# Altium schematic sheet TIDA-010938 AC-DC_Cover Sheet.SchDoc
size 431 x 279 mm; Date: Not shown in title block; ApprovedBy: Not shown in title block; CheckedBy: Not shown in title block; Author: Not shown in title block; CompanyName: Not shown in title block; Engineer: Not shown in title block; Organization: Not shown in title block; Address1: Not shown in title block; Address2: Not shown in title block; Address3: Not shown in title block; Address4: Not shown in title block; DocumentNumber: 8; Revision: Use project parameter SCH_Rev; SheetNumber: 2; SheetTotal: 11; PageSetup: Record=PageOptions¦CenterHorizontal=True¦CenterVertical=True¦PrintScale=1.00¦XCorrection=1.00¦YCorrection=1.00¦PrintKind=0¦BorderSize=5000000¦LeftOffset=0¦BottomOffset=0¦Orientation=2¦PaperLength=1000¦PaperWidth=1000¦Scale=100¦PaperSource=15¦PrintQuality=600¦MediaType=1¦DitherType=10¦PaperKind=Letter¦PrintScaleMode=1
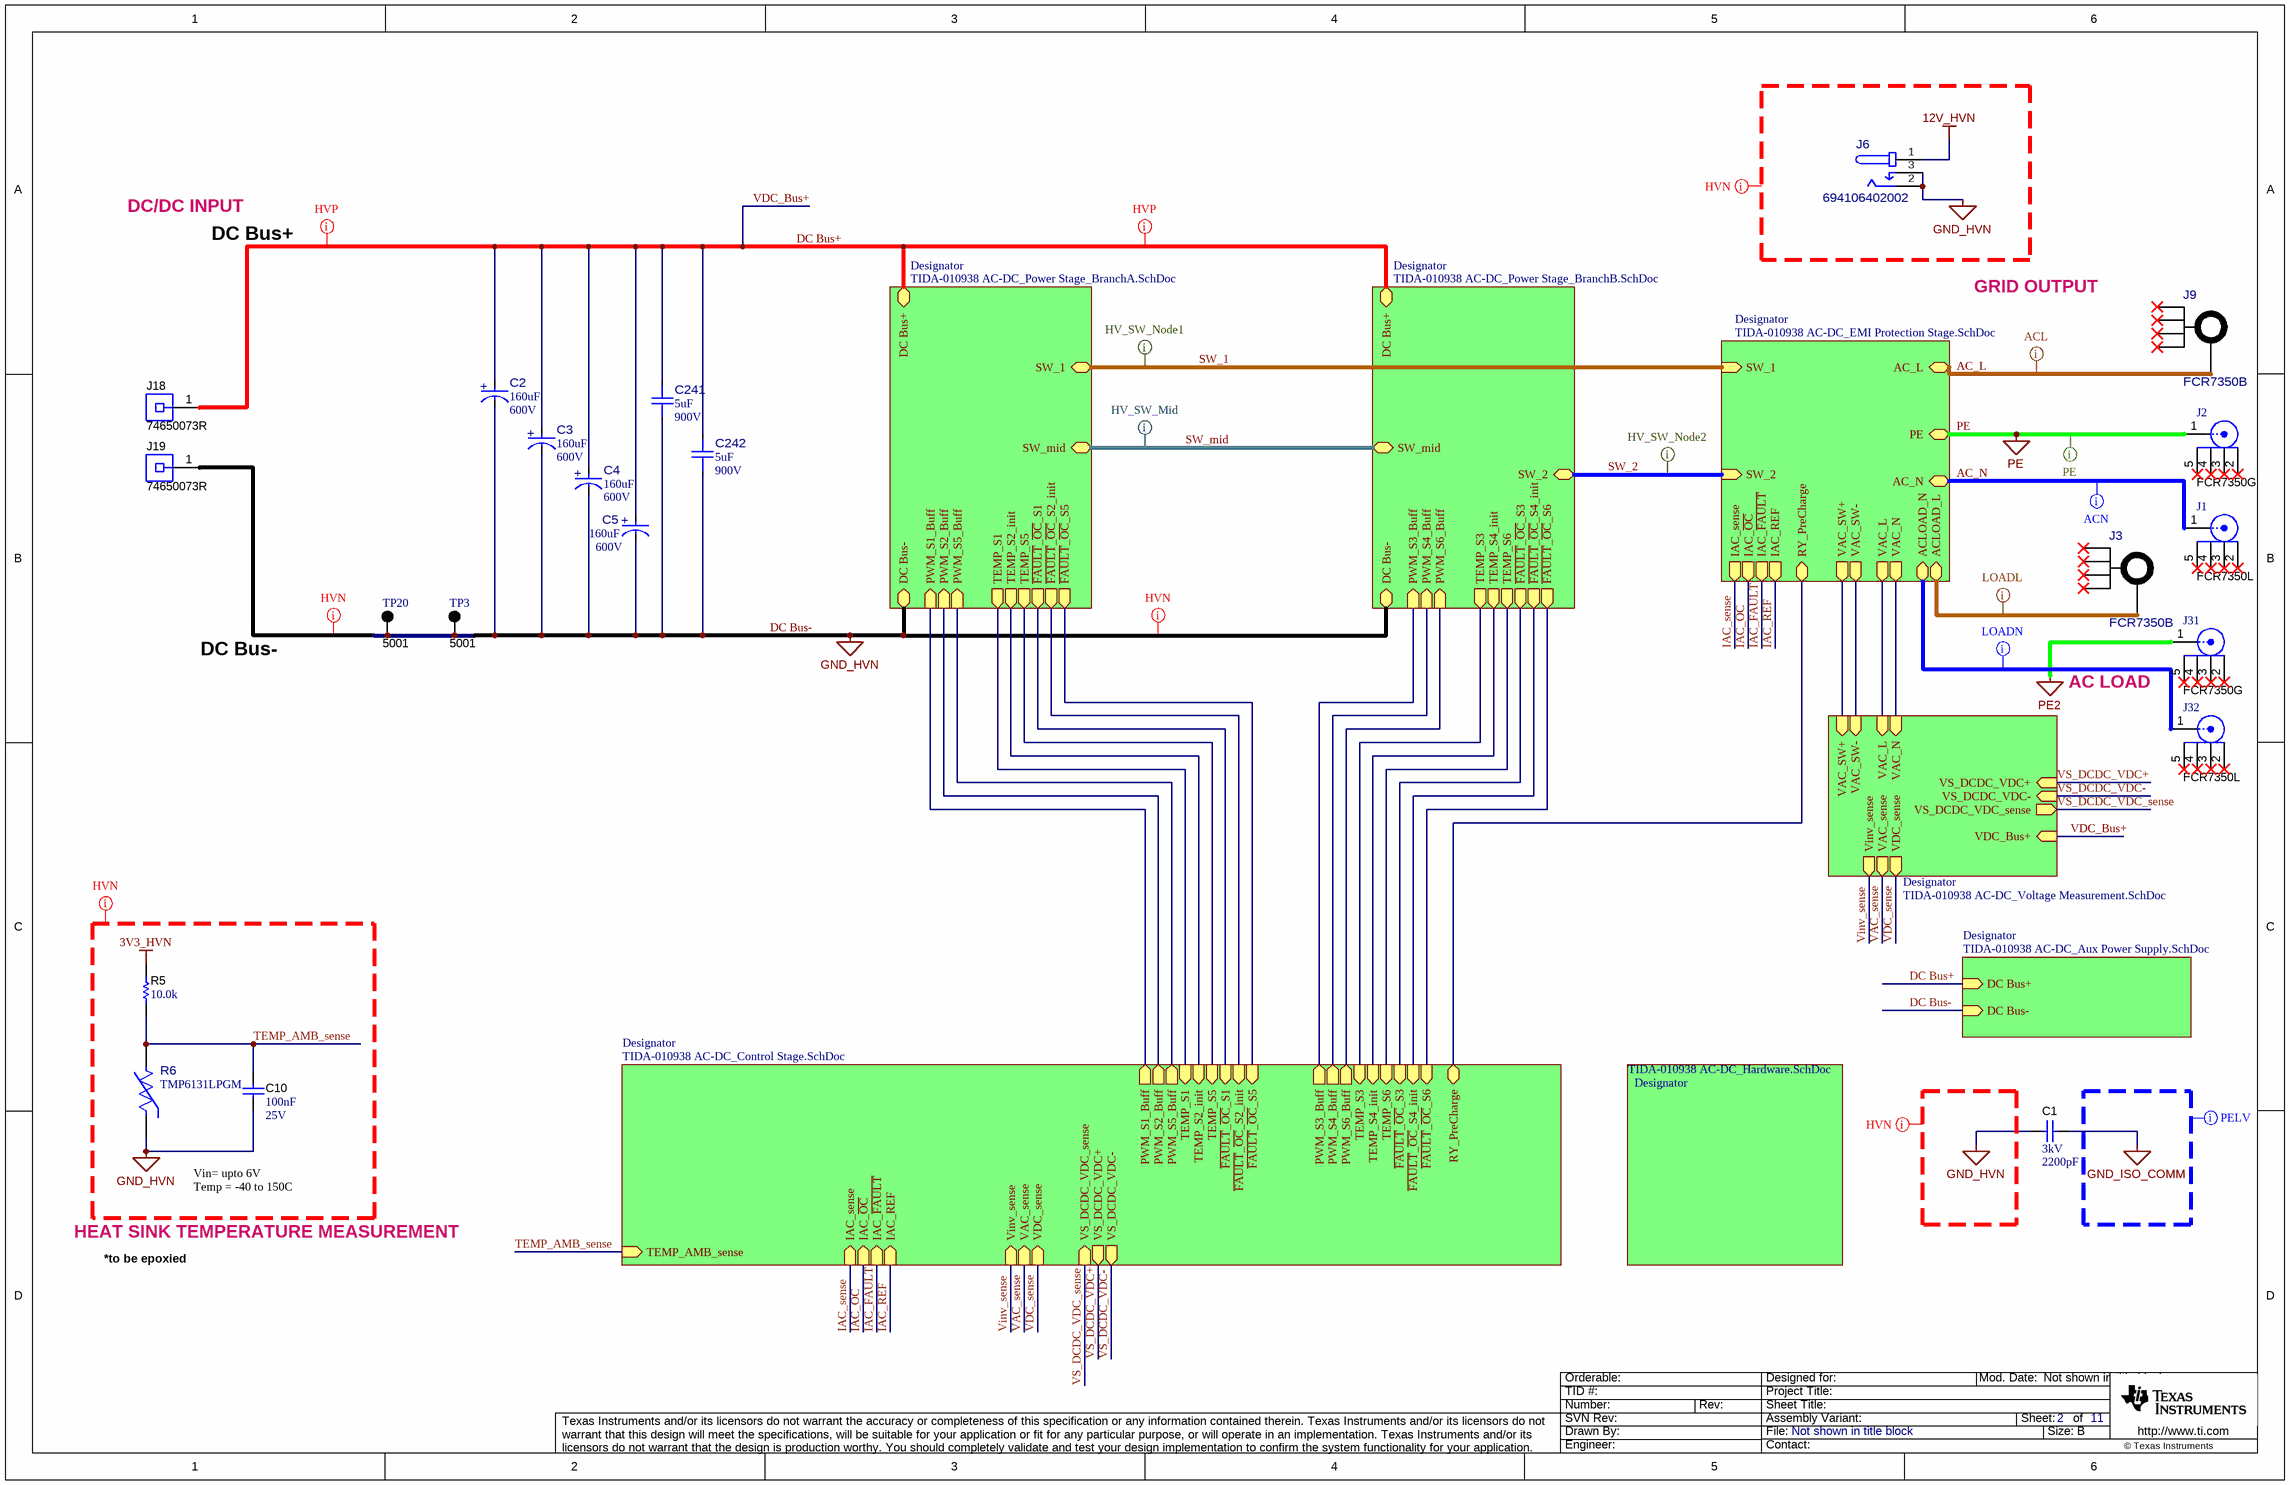
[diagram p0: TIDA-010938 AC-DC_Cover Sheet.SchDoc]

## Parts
C1  VDC_V: 3kV  ValueDisplayed: 2200pF  [CK45_1250x600x1650]  (hidden comment: CK45-B3FD222KYVNA)
C2  ValueDisplayed: 160uF  VDC_V: 600V  [FP-ALH82D161DD600_RADIAL-MFG]  (hidden comment: ALH82D161DD600)
C3  ValueDisplayed: 160uF  VDC_V: 600V  [FP-ALH82D161DD600_RADIAL-MFG]  (hidden comment: ALH82D161DD600)
C4  ValueDisplayed: 160uF  VDC_V: 600V  [FP-ALH82D161DD600_RADIAL-MFG]  (hidden comment: ALH82D161DD600)
C5  ValueDisplayed: 160uF  VDC_V: 600V  [FP-ALH82D161DD600_RADIAL-MFG]  (hidden comment: ALH82D161DD600)
C10  Cap_F: 100nF  VDC_V: 25V  [0603]  (hidden comment: 06033C104JAT2A)
C241  ValueDisplayed: 5uF  VDC_V: 900V  [FP-C4AKOBU4500A31J_RADIAL-MFG]  (hidden comment: C4AKOBU4500A31J)
C242  ValueDisplayed: 5uF  VDC_V: 900V  [FP-C4AKOBU4500A31J_RADIAL-MFG]  (hidden comment: C4AKOBU4500A31J)
J1  FCR7350L  [FP-FCR7350L_CONN_BANANA_JACK-MFG]
J2  FCR7350G  [FP-FCR7350G_CONN_BANANA_JACK-MFG]
J3  FCR7350B  [FP-FCR7350B_CONN_BANANA_JACK-MFG]
J6  694106402002  [FP-694106402002_CONN_PWR_10MM7_9MM0-MFG]
J9  FCR7350B  [FP-FCR7350B_CONN_BANANA_JACK-MFG]
J18  74650073R  [Wurth_WP-THRBU]
J19  74650073R  [Wurth_WP-THRBU]
J31  FCR7350G  [FP-FCR7350G_CONN_BANANA_JACK-MFG]
J32  FCR7350L  [FP-FCR7350L_CONN_BANANA_JACK-MFG]
R5  ValueDisplayed: 10.0k  [0603]  (hidden comment: RG1608P-103-B-T5)
R6  TMP6131LPGM  [LPG0002A-MFG]
TP3  5001  [Keystone5001]
TP20  5001  [Keystone5001]

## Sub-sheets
Designator = TIDA-010938 AC-DC_Power Stage_BranchA.SchDoc: TEMP_S5 (out), TEMP_S1 (out), DC Bus+ (bidir), SW_mid (bidir), SW_1 (bidir), DC Bus- (bidir), PWM_S1_Buff (in), PWM_S5_Buff (in), PWM_S2_Buff (in), TEMP_S2_init (out), ~{FAULT}_~{OC}_S5 (out), ~{FAULT}_~{OC}_S1 (out), ~{FAULT}_~{OC}_S2_init (out)
Designator = TIDA-010938 AC-DC_Power Stage_BranchB.SchDoc: TEMP_S6 (out), TEMP_S3 (out), DC Bus+ (bidir), SW_mid (bidir), SW_2 (bidir), DC Bus- (bidir), PWM_S6_Buff (in), PWM_S3_Buff (in), PWM_S4_Buff (in), TEMP_S4_init (out), ~{FAULT}_~{OC}_S6 (out), ~{FAULT}_~{OC}_S3 (out), ~{FAULT}_~{OC}_S4_init (out)
Designator = TIDA-010938 AC-DC_EMI Protection Stage.SchDoc: AC_L (bidir), AC_N (bidir), SW_1 (in), SW_2 (in), VAC_SW+ (out), VAC_SW- (out), VAC_L (out), VAC_N (out), IAC_sense (out), IAC_~{OC} (out), IAC_~{FAULT} (out), IAC_REF (out), RY_PreCharge (bidir), PE (bidir), ACLOAD_L (bidir), ACLOAD_N (bidir)
Designator = TIDA-010938 AC-DC_Voltage Measurement.SchDoc: VDC_sense (out), Vinv_sense (out), VAC_N (in), VAC_L (in), VAC_SW- (in), VAC_SW+ (in), VAC_sense (out), VDC_Bus+ (in), VS_DCDC_VDC+ (in), VS_DCDC_VDC- (in), VS_DCDC_VDC_sense (out)
Designator = TIDA-010938 AC-DC_Control Stage.SchDoc: IAC_REF (in), IAC_sense (in), VAC_sense (in), Vinv_sense (in), VDC_sense (in), TEMP_AMB_sense (in), PWM_S1_Buff (out), PWM_S2_Buff (out), PWM_S3_Buff (out), PWM_S4_Buff (out), PWM_S5_Buff (out), PWM_S6_Buff (out), TEMP_S2_init (in), TEMP_S4_init (in), RY_PreCharge (bidir), IAC_~{FAULT} (in), IAC_~{OC} (in), TEMP_S1 (in), TEMP_S3 (in), TEMP_S5 (in), TEMP_S6 (in), ~{FAULT}_~{OC}_S5 (in), ~{FAULT}_~{OC}_S6 (in), ~{FAULT}_~{OC}_S1 (in), ~{FAULT}_~{OC}_S3 (in), ~{FAULT}_~{OC}_S2_init (in), ~{FAULT}_~{OC}_S4_init (in), VS_DCDC_VDC_sense (in), VS_DCDC_VDC+ (out), VS_DCDC_VDC- (out)
Designator = TIDA-010938 AC-DC_Hardware.SchDoc: no entries
Designator = TIDA-010938 AC-DC_Aux Power Supply.SchDoc: DC Bus+ (in), DC Bus- (in)

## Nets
3V3_HVN: R5.2
12V_HVN: J6.1
DC Bus-: C1.2 C2.1(CATHODE) C3.1(CATHODE) C4.1(CATHODE) C5.1(CATHODE) C10.2 C241.1 C242.1 J6.2 J6.3 J19.1 R6.2(+) TP3.1 TP20.1 ; sheet Designator/DC Bus-, sheet Designator/DC Bus-, sheet Designator/DC Bus-  [also labelled GND_HVN]
GND_ISO_COMM: C1.1
PE: J2.1 ; sheet Designator/PE
PE2: J31.1
AC_L: J9.1 ; sheet Designator/AC_L
AC_N: J1.1 ; sheet Designator/AC_N
DC Bus+: C2.2(ANODE) C3.2(ANODE) C4.2(ANODE) C5.2(ANODE) C241.2 C242.2 J18.1 ; sheet Designator/DC Bus+, sheet Designator/DC Bus+, sheet Designator/VDC_Bus+, sheet Designator/DC Bus+  [also labelled VDC_Bus+]
IAC_~{FAULT}: sheet Designator/IAC_~{FAULT}, sheet Designator/IAC_~{FAULT}
IAC_~{OC}: sheet Designator/IAC_~{OC}, sheet Designator/IAC_~{OC}
IAC_REF: sheet Designator/IAC_REF, sheet Designator/IAC_REF
IAC_sense: sheet Designator/IAC_sense, sheet Designator/IAC_sense
SW_1: sheet Designator/SW_1, sheet Designator/SW_1
SW_2: sheet Designator/SW_2, sheet Designator/SW_2
SW_mid: sheet Designator/SW_mid, sheet Designator/SW_mid
TEMP_AMB_sense: C10.1 R5.1 R6.1(-) ; sheet Designator/TEMP_AMB_sense
VAC_sense: sheet Designator/VAC_sense, sheet Designator/VAC_sense
VDC_sense: sheet Designator/VDC_sense, sheet Designator/VDC_sense
Vinv_sense: sheet Designator/Vinv_sense, sheet Designator/Vinv_sense
VS_DCDC_VDC+: sheet Designator/VS_DCDC_VDC+, sheet Designator/VS_DCDC_VDC+
VS_DCDC_VDC-: sheet Designator/VS_DCDC_VDC-, sheet Designator/VS_DCDC_VDC-
VS_DCDC_VDC_sense: sheet Designator/VS_DCDC_VDC_sense, sheet Designator/VS_DCDC_VDC_sense
NetJ3_1: J3.1 ; sheet Designator/ACLOAD_L
NetJ32_1: J32.1 ; sheet Designator/ACLOAD_N
(unnamed): sheet Designator/TEMP_S5, sheet Designator/TEMP_S5
(unnamed): sheet Designator/TEMP_S1, sheet Designator/TEMP_S1  [a separate net that carries the same name]
(unnamed): sheet Designator/PWM_S1_Buff, sheet Designator/PWM_S1_Buff  [a separate net that carries the same name]
(unnamed): sheet Designator/PWM_S5_Buff, sheet Designator/PWM_S5_Buff  [a separate net that carries the same name]
(unnamed): sheet Designator/PWM_S2_Buff, sheet Designator/PWM_S2_Buff  [a separate net that carries the same name]
(unnamed): sheet Designator/TEMP_S2_init, sheet Designator/TEMP_S2_init  [a separate net that carries the same name]
(unnamed): sheet Designator/~{FAULT}_~{OC}_S5, sheet Designator/~{FAULT}_~{OC}_S5  [a separate net that carries the same name]
(unnamed): sheet Designator/~{FAULT}_~{OC}_S1, sheet Designator/~{FAULT}_~{OC}_S1  [a separate net that carries the same name]
(unnamed): sheet Designator/~{FAULT}_~{OC}_S2_init, sheet Designator/~{FAULT}_~{OC}_S2_init  [a separate net that carries the same name]
(unnamed): sheet Designator/TEMP_S6, sheet Designator/TEMP_S6  [a separate net that carries the same name]
(unnamed): sheet Designator/TEMP_S3, sheet Designator/TEMP_S3  [a separate net that carries the same name]
(unnamed): sheet Designator/PWM_S6_Buff, sheet Designator/PWM_S6_Buff  [a separate net that carries the same name]
(unnamed): sheet Designator/PWM_S3_Buff, sheet Designator/PWM_S3_Buff  [a separate net that carries the same name]
(unnamed): sheet Designator/PWM_S4_Buff, sheet Designator/PWM_S4_Buff  [a separate net that carries the same name]
(unnamed): sheet Designator/TEMP_S4_init, sheet Designator/TEMP_S4_init  [a separate net that carries the same name]
(unnamed): sheet Designator/~{FAULT}_~{OC}_S6, sheet Designator/~{FAULT}_~{OC}_S6  [a separate net that carries the same name]
(unnamed): sheet Designator/~{FAULT}_~{OC}_S3, sheet Designator/~{FAULT}_~{OC}_S3  [a separate net that carries the same name]
(unnamed): sheet Designator/~{FAULT}_~{OC}_S4_init, sheet Designator/~{FAULT}_~{OC}_S4_init  [a separate net that carries the same name]
(unnamed): sheet Designator/VAC_SW+, sheet Designator/VAC_SW+  [a separate net that carries the same name]
(unnamed): sheet Designator/VAC_SW-, sheet Designator/VAC_SW-  [a separate net that carries the same name]
(unnamed): sheet Designator/VAC_L, sheet Designator/VAC_L  [a separate net that carries the same name]
(unnamed): sheet Designator/VAC_N, sheet Designator/VAC_N  [a separate net that carries the same name]
(unnamed): sheet Designator/RY_PreCharge, sheet Designator/RY_PreCharge  [a separate net that carries the same name]

Not connected (* = marked no-connect by the designer): J1 2* 3* 4* 5*; J2 2* 3* 4* 5*; J3 2(MNT_1)* 3(MNT_2)* 4(MNT_3)* 5(MNT_4)*; J9 2(MNT_1)* 3(MNT_2)* 4(MNT_3)* 5(MNT_4)*; J31 2* 3* 4* 5*; J32 2* 3* 4* 5*

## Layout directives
net class HVN: 3V3_HVN, 12V_HVN, DC Bus-, GND_HVN, TEMP_AMB_sense
net class HVP: DC Bus+
net class PELV: GND_ISO_COMM
net class ACL: AC_L
net class ACN: AC_N
net class PE: PE
net class HV_SW_Node1: SW_1
net class HV_SW_Mid: SW_mid
net class HV_SW_Node2: SW_2
net class LOADL: NetJ3_1
net class LOADN: NetJ32_1

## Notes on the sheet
- DC/DC INPUT
- DC Bus+
- GRID OUTPUT
- DC Bus-
- AC LOAD
- Vin= upto 6V
  Temp = -40 to 150C
- HEAT SINK TEMPERATURE MEASUREMENT
- *to be epoxied

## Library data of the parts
C1 = CMP-0086078-1: CAP, CERM, 2200 pF, 3000 V,+/- 10%, B, Dia 12.5mm; Manufacturer: TDK; AEC Qualified: N; SizeAreaWB_mm2: 116; Cap_Case: 12.5x6x16.5mm; SizeZ_mm: 16.5; AEC Category: Q200; TaMin_C: -25°C; SizeX_mm: 12.5; SizeY_mm: 6; Value2: 3000V; TaMax_C: 105°C; Value: 2200pF; SizeArea_mm2: 75; U/M: EA; Cap_F: 2.2nF
C2-C5 = CMP-0033686-1: ALH82, Aluminum Electrolytic, 160 uF, 20%, 600 VDC, -40/+105°C; Manufacturer: KEMET; AEC Qualified: No; Cap_F: 160µF; IRMS_A: 4.51A; SizeZ_mm: 42mm; Esr: 0.877; Leakage Current: 288uA; Life: 3000Hours; Value: 160µF
C10 = CMP-0006752-5: CAP, CERM, 0.1 uF, 25 V, +/- 5%, X7R, 0603; Manufacturer: AVX; TaMin_C: -55°C; ESR_ohm: 0.05; Polarized: N; SizeAreaWB_mm2: 4.68; Value1: 0.05 ohm; U/M: EA; Value: 0.1uF; TaMax_C: 125°C; SizeZ_mm: 1; SizeX_mm: 1.6; SizeY_mm: 0.8; SizeArea_mm2: 1.28; AEC Category: Q200
C241 C242 = CMP-0037193-1: 5 µF Film Capacitor 900V Polypropylene (PP), Metallized Radial; Manufacturer: Kemet; AEC Grade: Grade 1; AEC Qualified: No; Cap_F: 5µF; SizeZ_mm: 29.7mm; Tolerance_%: 5%; Standoff Height: 0.5mm; Value: 5µF
J1 J32 = CMP-0098295-2: Banana Test Connector, 4mm, Socket, PCB Mount, 24 A, 1 kV, Gold Plated Contacts, Blue; Manufacturer: CLIFF Electronic Components; Current_A: 24A; Voltage_V: 1kV; AEC Qualified: No; Conn Orientation: Right Angle; SizeZ_mm: 11.6mm; Standoff Height: 0.7mm
J2 J31 = CMP-0098294-2: Banana Test Connector, Socket, PCB Mount, 24 A, 1 kV, Gold Plated Contacts, Green; Manufacturer: CLIFF Electronic Components; Current_A: 24A; Voltage_V: 1kV; AEC Qualified: No; Conn Orientation: Right Angle; SizeZ_mm: 11.6mm; Standoff Height: 0.7mm
J3 J9 = CMP-0032021-2: Banana Jack Connector Standard Banana Solder Black; Manufacturer: CLIFF Electronic Components; ContactFinish: Gold; Current_A: 24A; Voltage_V: 1kV; AEC Qualified: No; Conn Orientation: Horizontal; Is Female: yes; SizeZ_mm: 12.5mm; Standoff Height: 0.7mm
J6 = CMP-0040211-1: Power Barrel Connector Jack 2.10mm ID (0.083"), 5.50mm OD (0.217") Through Hole; Manufacturer: Wurth Electronics; ContactFinish: Gold; Current_A: 3A; Voltage_V: 30V; AEC Qualified: No; Conn Gender: Female; Conn Orientation: Vertical; SizeZ_mm: 14.3mm
J18 J19 = CMP-0078526-1: Power Element Bush, M3, TH; Manufacturer: Wurth Elektronik; Gender: Female; Current_A: 50A; ContactFinish: Tin; CompType: Screw Terminal
R5 = CMP-0023404-3: RES, 10.0 k, 0.1%, 0.1 W, 0603; Manufacturer: Susumu Co Ltd; Power_W: 100mW; TempCo: 25 ppm/C; Value_Code: 10k0; U/M: EA; Value: 10.0k; EIA_Code: E192; Res_ohm: 10k; SizeX_mm: 1.6; SizeY_mm: 0.8; SizeZ_mm: 1; Value2: 0.1W; SizeArea_mm2: 1.28; VDC_V: 75V; AEC Category: Q200
R6 = CMP-0089579-1: SENSOR PTC 10K OHM 1% TO92S; Manufacturer: Texas Instruments; TJmax_C: +155°C; AEC Qualified: No; Value: 10kΩ; SizeZ_mm: 5.05mm; Max Current: 400uA; TaMax_C: +150°C; TempCo: 6400ppm/°C; TaMin_C: -40°C; VDC_V: 5.5V
TP3 TP20 = CMP-0055138-2: Test Point, Miniature, Black, TH; Manufacturer: Keystone Electronics; ContactFinish: Silver; CNHeader: FALSE; Green_Lifecycle: Active; Green_REACh: Passed; CT: TRUE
